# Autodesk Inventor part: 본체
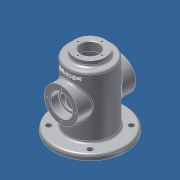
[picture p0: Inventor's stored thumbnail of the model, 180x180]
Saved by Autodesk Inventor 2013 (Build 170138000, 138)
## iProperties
Created: 2014-12
Part Number: 본체
Material: 알루미늄 6061
Document SubType Name: Modeling
Designer: CAD-B31
Density: 2.71 g/cm^3
Mass: 479.601 g
Surface Area: 607.45 cm^2
Volume: 176.974 cm^3
Author: CAD-B31
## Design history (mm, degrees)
sketch "스케치1"
  geometry: C1 r 32.5 at (0, 0); 1 further point
  constraints: 1 centre point, 1 coincident
  dimensions: "d0" = 65 diameter of C1
extrude "돌출1" new body sketch "스케치1" distance "d1" = 90; taper "d2" = 0 deg
sketch "스케치2"
  geometry: C1 r 52.5 at (0, 0); 1 further point
  constraints: 1 centre point
  dimensions: "d5" = 105 diameter of C1
extrude "돌출2" join sketch "스케치2" distance "d6" = 8; taper "d7" = 0 deg
sketch "스케치3"
  geometry: C1 r 27.5 at (0, 0); 1 further point
  constraints: 1 centre point, 1 coincident
  dimensions: "d8" = 55 diameter of C1
extrude "돌출3" cut sketch "스케치3" distance "d10" = 93; taper "d11" = 0 deg
node "작업 평면1"
sketch "스케치4"
  geometry: C1 r 22.5 at (0, 0); 1 further point
  constraints: 1 centre point, 1 coincident
  dimensions: "d13" = 45 diameter of C1
extrude "돌출4" join sketch "스케치4" stored distance "d15" = 93; taper "d16" = 0 deg
node "작업 평면2"
sketch "스케치5"
  geometry: L1 (-52.5, -8)-(52.5, -8) reference; L2 (-69, 47)-(69, 47); L3 (32.5, 90)-(-32.5, 90) reference; C1 r 25 at (0, 47); 2 further points
  constraints: 2 end point, 2 midpoint, 1 centre point, 1 parallel, 1 vertical alignment
  dimensions: "d18" = 55 distance between parallel lines of L2 L1; "d19" = 50 diameter of C1
extrude "돌출5" join sketch "스케치5" stored distance "d20" = 93; taper "d21" = 0 deg
hole "구멍1" diameter "d24" = 25; stored, may be unused: countersink angle "d28" = 90 deg, drill point angle "d30" = 0 deg; dims "d22" = 10, "d23" = 10, "d25" = 6, "d26" = 32, "d27" = 12, "d29" = 8
hole "구멍2" diameter "d33" = 27; stored, may be unused: countersink angle "d37" = 90 deg, drill point angle "d39" = 0 deg; dims "d31" = 10, "d32" = 10, "d34" = 6, "d35" = 32, "d36" = 12, "d38" = 8
sketch "스케치7" dims "d40" = 86
  geometry: L1 (69.5, 0)-(-69.5, 0); L2 (-58.776, 58.776)-(58.776, -58.776); 5 further points
  constraints: 4 end point, 3 coincident, 2 midpoint, 1 horizontal, 1 point on line, 3 other
  dimensions: "d41" = 45 deg angle of L2 L1
hole "구멍3" sketch "스케치7" at (30.406, -30.406) diameter "d43" = 8; stored, may be unused: countersink angle "d47" = 90 deg, drill point angle "d49" = 0 deg; dims "d44" = 6, "d45" = 32, "d46" = 12, "d48" = 8
sketch "스케치8"
  geometry: A1 r 17.5 centre (0, 0) between (0, 17.5) and (0, -17.5); 3 further points
  constraints: 4 point on circle, 1 centre point, 1 coincident
  dimensions: "d53" = 35 diameter of A1
hole "구멍4" sketch "스케치8" at (0, 17.5), (0, -17.5), (17.5, 0), (-17.5, 0) diameter "d55" = 2.459; stored, may be unused: countersink angle "d59" = 90 deg, drill point angle "d61" = 118 deg; dims "d56" = 6, "d57" = 32, "d58" = 12, "d60" = 8
sketch "스케치9"
  geometry: C1 r 16 at (0, 0) reference; C2 r 25 at (0, 0) reference; A1 r 20.5 centre (0, 0) between (0, -20.5) and (20.5, 0); 3 further points
  constraints: 4 point on circle, 1 centre point, 1 coincident
  dimensions: "d62" = 41 diameter of A1
hole "구멍5" sketch "스케치9" at (0, -20.5), (20.5, 0), (0, 20.5), (-20.5, 0) diameter "d64" = 2.459; stored, may be unused: countersink angle "d68" = 90 deg, drill point angle "d70" = 118 deg; dims "d65" = 6, "d66" = 32, "d67" = 12, "d69" = 8
sketch "스케치10"
  geometry: L1 (-32.5, -43)-(32.5, -43) reference; 3 further points
  constraints: 1 midpoint, 1 vertical alignment, 1 other
  dimensions: "d71" = 9 distance from line of point (0, -34) L1
feature "엠보싱1" sketch "스케치10" dims "d72" = 1, "d73" = 0
fillet "모깎기1" dims "d74" = 0.3
fillet "모깎기2" dims "d75" = 3
chamfer "모따기1" distance "d77" = 1; stored, may be unused: second distance "d78" = 2, angle "d79" = 45 deg
node "솔리드1"
mirror "대칭1"
pattern_circular "원형 패턴1" dims angle "d51" = 360 deg
mirror "대칭2"
node "투영된 루프1"
other parameters: "d12" = -106, "d17" = 42.5
